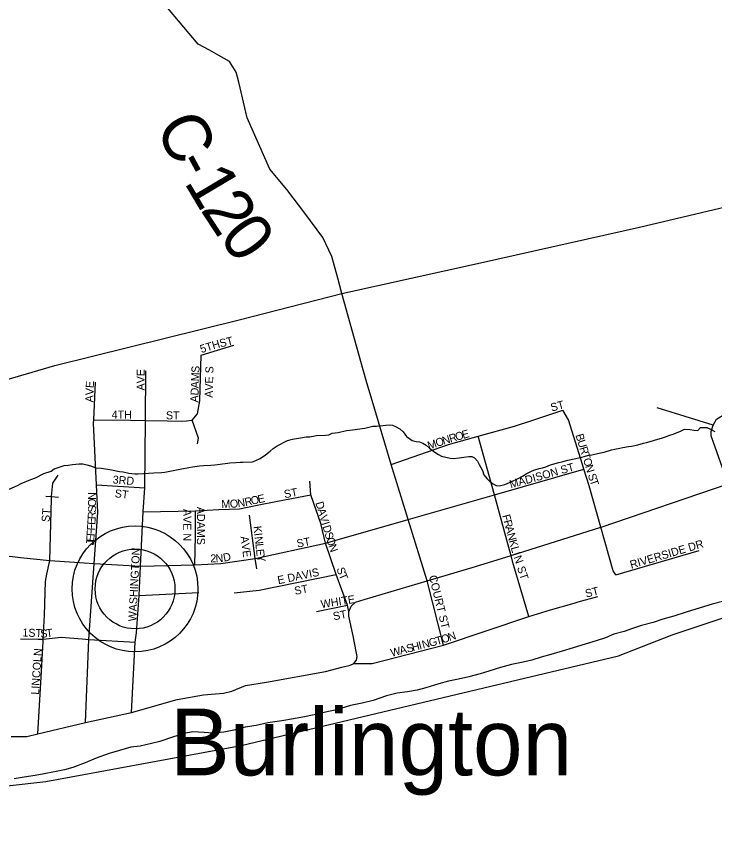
# Model space of a CAD drawing. Extents: x 0 to 34, y 0 to 22.
# Drawn here: x 6.591 to 7.417, y 14.808 to 15.766 of the extents above; entities that cross this region are included whole.
import ezdxf

# ---------------------------------------------------------------- set-up
doc = ezdxf.new("R2010")
doc.units = 0
for name, color, linetype in [('GM_X_County', 7, 'Continuous'), ('GM_X_County_Road', 7, 'Continuous'), ('GM_X_County_Road_Text', 7, 'Continuous'), ('GM_X_Major_River', 7, 'Continuous'), ('GM_X_Minor_River', 7, 'Continuous'), ('GM_X_Township', 7, 'Continuous'), ('GM_X_Township_ROW', 7, 'Continuous'), ('GM_X_Township_Subdivision', 7, 'Continuous'), ('GM_X_Township_Subdivision_Text', 7, 'Continuous'), ('GM_X_Unincorporated', 7, 'Continuous'), ('GM_X_Unincorporated_Location', 7, 'Continuous'), ('GM_X_Unincorporated_Text', 7, 'Continuous'), ('GM_X_US_Route', 7, 'Continuous')]:
    doc.layers.add(name, color=color, linetype=linetype)

msp = doc.modelspace()

# ---------------------------------------------------------------- linework, layer by layer
at = {"layer": 'GM_X_County'}
msp.add_lwpolyline([(5.81192, 14.81413), (6.12839, 14.80806), (6.29418, 14.8107), (6.34339, 14.82245), (6.49177, 14.84672), (6.62577, 14.8615), (6.85666, 14.90434), (7.30292, 15.01013), (7.36651, 15.03516), (7.82526, 15.188), (8.21322, 15.33138), (8.33283, 15.3731), (8.56485, 15.46794), (8.67596, 15.52844), (8.71954, 15.55584), (8.73927, 15.56156), (8.7787, 15.57074), (8.80562, 15.58596), (8.8602, 15.61489), (8.89736, 15.6271), (8.90844, 15.63)], dxfattribs=at)
at = {"layer": 'GM_X_County_Road'}
for points in [[(6.97083, 15.45674), (6.96374, 15.4824), (6.95339, 15.50483), (6.93213, 15.53357), (6.91086, 15.56173), (6.89067, 15.58562), (6.86378, 15.64638), (6.85395, 15.68852), (6.85092, 15.7003), (6.84296, 15.71283), (6.83047, 15.72005), (6.8191, 15.72613), (6.80585, 15.73336), (6.74869, 15.80174), (6.73004, 15.82879), (6.72032, 15.83957), (6.70903, 15.85296), (6.70404, 15.8632), (6.69721, 15.8837), (6.69035, 15.92085), (6.67921, 15.95173), (6.67768, 15.9594)], [(7.43274, 15.21354), (7.41236, 15.27022), (7.41271, 15.2754), (7.41478, 15.283), (7.41892, 15.28991), (7.42583, 15.29441), (7.43344, 15.29718), (7.46008, 15.30495), (7.46522, 15.30754), (7.46928, 15.31127), (7.47215, 15.32564), (7.4756, 15.4004), (7.47906, 15.44986), (7.48047, 15.48073), (7.48111, 15.55316)], [(7.00092, 15.34833), (6.9758, 15.43872), (6.97083, 15.45674)], [(7.07651, 15.09894), (7.05417, 15.17138), (7.0341, 15.23643), (7.01146, 15.31226), (7.00514, 15.33313), (7.00092, 15.34833)], [(6.99266, 15.00455), (6.9932, 15.00522), (6.99394, 15.00942), (6.9927, 15.01536), (6.98924, 15.0339), (6.98405, 15.05715), (6.98405, 15.0621), (6.98677, 15.06902), (6.99171, 15.07347), (7.00209, 15.07693), (7.07651, 15.09894), (7.13369, 15.11586), (7.17588, 15.12878), (7.28203, 15.16234), (7.28244, 15.16247), (7.43274, 15.21354)], [(6.58485, 14.91492), (6.60306, 14.91492), (6.61621, 14.91796), (6.67252, 14.93145), (6.72714, 14.94325), (6.78109, 14.95843), (6.81211, 14.96416), (6.83572, 14.96619), (6.84583, 14.96821), (6.86201, 14.97495), (6.88669, 14.97903), (6.9564, 14.99171), (6.97587, 14.9967), (6.98554, 14.99928), (6.98998, 15.00126), (6.99266, 15.00455)]]:
    msp.add_lwpolyline(points, dxfattribs=at)
at = {"layer": 'GM_X_Major_River'}
for points in [[(7.42732, 15.07476), (7.4137, 15.07135), (7.39933, 15.0668), (7.38307, 15.06187), (7.36832, 15.05695), (7.35546, 15.05354), (7.34374, 15.04975), (7.33012, 15.04596), (7.31953, 15.04255), (7.3097, 15.03914), (7.29722, 15.03574), (7.28739, 15.03157), (7.27642, 15.02778), (7.26356, 15.02399), (7.24919, 15.01982), (7.23633, 15.01566), (7.2231, 15.01187), (7.21137, 15.00846), (7.20041, 15.00505), (7.19019, 15.00278), (7.1762, 14.99975), (7.16334, 14.99634), (7.14973, 14.99217), (7.13914, 14.98876), (7.12591, 14.98535), (7.1138, 14.9827), (7.10208, 14.98005), (7.09036, 14.97702), (7.07523, 14.97248), (7.06464, 14.96945), (7.0533, 14.96755), (7.04119, 14.96604), (7.02871, 14.96301), (7.01283, 14.95733), (6.99997, 14.9543), (6.98598, 14.95127), (6.96934, 14.94634), (6.95648, 14.94369), (6.94665, 14.94104), (6.93341, 14.93839), (6.91866, 14.93574), (6.90467, 14.93347), (6.88841, 14.93082), (6.87442, 14.92779), (6.86156, 14.9259), (6.84794, 14.92249), (6.83622, 14.91984), (6.82336, 14.91871), (6.81278, 14.91947), (6.79954, 14.92023), (6.78933, 14.91834), (6.77534, 14.91417), (6.76059, 14.90887), (6.75076, 14.9066), (6.73714, 14.90357), (6.72617, 14.90205), (6.71294, 14.89827), (6.70045, 14.89486), (6.68533, 14.88917), (6.67209, 14.88349), (6.65772, 14.87819)], [(6.65772, 14.87819), (6.64789, 14.87553), (6.63578, 14.87288), (6.62368, 14.87061), (6.61309, 14.86872), (6.60024, 14.86683), (6.58813, 14.86494)]]:
    msp.add_lwpolyline(points, dxfattribs=at)
at = {"layer": 'GM_X_Minor_River'}
for points in [[(6.58251, 15.20737), (6.59205, 15.21176), (6.59664, 15.21396), (6.60809, 15.2187), (6.61342, 15.22051), (6.62336, 15.22565), (6.63212, 15.22854), (6.63558, 15.23114), (6.64739, 15.23512), (6.65195, 15.2358), (6.65726, 15.23647), (6.66106, 15.23678), (6.66523, 15.23709), (6.66939, 15.23702), (6.6743, 15.23617), (6.67845, 15.23496), (6.68484, 15.23258), (6.69127, 15.23209), (6.69883, 15.23082), (6.70336, 15.22998), (6.7128, 15.2283), (6.71734, 15.22784), (6.72375, 15.22622), (6.73093, 15.22533), (6.73472, 15.22527), (6.74761, 15.22619), (6.7533, 15.22647), (6.7624, 15.22707), (6.76657, 15.22738), (6.77417, 15.22877), (6.78216, 15.23053), (6.78671, 15.23121), (6.7947, 15.23298), (6.79926, 15.23366), (6.80723, 15.23466), (6.81216, 15.23534), (6.82088, 15.23556), (6.82543, 15.23587), (6.82885, 15.23657), (6.83796, 15.23755), (6.84327, 15.23822), (6.85048, 15.23886), (6.85541, 15.23915), (6.85882, 15.23909), (6.87019, 15.23966), (6.87401, 15.24111), (6.87898, 15.24368), (6.88549, 15.24775), (6.89087, 15.25221), (6.89471, 15.25519), (6.89931, 15.25852), (6.91154, 15.26477), (6.91725, 15.26619), (6.92675, 15.26793), (6.93359, 15.26895), (6.93776, 15.26926), (6.94573, 15.27064), (6.95635, 15.27122), (6.96052, 15.27153), (6.96434, 15.27336), (6.97156, 15.27438), (6.98144, 15.27648), (6.98524, 15.27718), (6.99169, 15.27783), (6.99967, 15.27883), (7.00309, 15.27953), (7.01222, 15.28165), (7.01676, 15.28158), (7.02094, 15.28226), (7.02435, 15.28259), (7.02777, 15.28291), (7.03232, 15.28321), (7.03572, 15.28277), (7.0391, 15.28119), (7.04435, 15.27845), (7.04808, 15.27496), (7.05215, 15.26958), (7.05889, 15.26491), (7.06379, 15.26368), (7.06757, 15.26324), (7.07171, 15.26165), (7.07545, 15.25931), (7.07956, 15.25582), (7.08592, 15.25116), (7.09003, 15.24805), (7.09378, 15.24608), (7.09869, 15.24524), (7.10397, 15.24401), (7.10775, 15.24357), (7.11458, 15.24421), (7.1199, 15.24526), (7.12597, 15.24591), (7.12938, 15.24585), (7.13276, 15.24428), (7.1361, 15.24042)], [(7.1361, 15.24042), (7.1383, 15.23621), (7.14197, 15.22931), (7.14378, 15.22434), (7.1471, 15.21973), (7.1512, 15.21586), (7.15457, 15.21353), (7.15832, 15.21157), (7.16172, 15.21113), (7.16857, 15.21291), (7.17659, 15.21619), (7.18346, 15.21949), (7.18958, 15.2228), (7.19379, 15.22539), (7.20067, 15.22907), (7.2041, 15.23015), (7.20905, 15.23158), (7.21324, 15.23265), (7.21704, 15.23372), (7.22238, 15.23591), (7.23228, 15.23878), (7.23608, 15.23947), (7.24294, 15.24163), (7.25244, 15.24337), (7.25967, 15.24515), (7.26804, 15.24728), (7.27146, 15.24798), (7.27792, 15.24939), (7.28591, 15.25115), (7.29466, 15.25366), (7.29809, 15.25436), (7.30455, 15.25577), (7.30797, 15.25647), (7.31481, 15.25787), (7.31823, 15.25819), (7.32583, 15.25958), (7.33268, 15.26174), (7.3361, 15.26244), (7.34333, 15.26422), (7.34677, 15.26568), (7.35361, 15.26746), (7.35743, 15.26891), (7.36353, 15.27109), (7.36771, 15.27216), (7.37611, 15.27581), (7.38107, 15.278), (7.38751, 15.27789), (7.39204, 15.27706), (7.39658, 15.2766), (7.40004, 15.27996), (7.40725, 15.28021), (7.41176, 15.27824), (7.41701, 15.27549)]]:
    msp.add_lwpolyline(points, dxfattribs=at)
at = {"layer": 'GM_X_Township'}
msp.add_lwpolyline([(5.81192, 14.81413), (6.12839, 14.80806), (6.29418, 14.8107), (6.34339, 14.82245), (6.49177, 14.84672), (6.62577, 14.8615), (6.85666, 14.90434), (7.30292, 15.01013), (7.36651, 15.03516), (7.82526, 15.188), (8.21322, 15.33138), (8.33283, 15.3731), (8.56485, 15.46794), (8.67596, 15.52844), (8.71954, 15.55584), (8.73927, 15.56156), (8.7787, 15.57074), (8.80562, 15.58596), (8.8602, 15.61489), (8.89736, 15.6271), (8.90844, 15.63)], dxfattribs=at)
at = {"layer": 'GM_X_Township_ROW'}
msp.add_lwpolyline([(7.41478, 15.283), (7.34853, 15.30357)], dxfattribs=at)
at = {"layer": 'GM_X_Township_Subdivision'}
for points in [[(6.80958, 15.36552), (6.84821, 15.37763)], [(6.80501, 15.26077), (6.80615, 15.2676), (6.79858, 15.28885), (6.80501, 15.29644), (6.80767, 15.31162), (6.80958, 15.36552)], [(6.72714, 14.94325), (6.73119, 15.02622), (6.73287, 15.03735), (6.73625, 15.08154), (6.73778, 15.1162), (6.74064, 15.18055), (6.74291, 15.20866), (6.74356, 15.28837), (6.74404, 15.34696)], [(6.68225, 15.2858), (6.68242, 15.28929), (6.68456, 15.33371)], [(7.20034, 15.28849), (7.23713, 15.30057)], [(7.26018, 15.23651), (7.24396, 15.28903), (7.23713, 15.30057)], [(6.68242, 15.28929), (6.726, 15.28864)], [(6.726, 15.28864), (6.72607, 15.28863), (6.74356, 15.28837), (6.76958, 15.28798)], [(6.76958, 15.28798), (6.76972, 15.28798), (6.78645, 15.28772), (6.79214, 15.28809), (6.79858, 15.28885)], [(7.0341, 15.23643), (7.10206, 15.25995), (7.13711, 15.26979), (7.17985, 15.28176), (7.20034, 15.28849)], [(6.67252, 14.93145), (6.67657, 15.0296), (6.68293, 15.11931), (6.6872, 15.17964), (6.68565, 15.21245), (6.68222, 15.28518), (6.68225, 15.2858)], [(7.17444, 15.13407), (7.15631, 15.20063), (7.13711, 15.26979)], [(6.95662, 15.14343), (7.05417, 15.17138), (7.15631, 15.20063), (7.26192, 15.23088)], [(7.29964, 15.10583), (7.29652, 15.11068), (7.28203, 15.16234), (7.26833, 15.21121), (7.26192, 15.23088), (7.26018, 15.23651)], [(6.63249, 15.19572), (6.63257, 15.1985), (6.63412, 15.21417), (6.64031, 15.22365)], [(6.68565, 15.21245), (6.74291, 15.20866)], [(6.95133, 15.1649), (6.9512, 15.16542), (6.93912, 15.2005), (6.93776, 15.21682)], [(6.89982, 15.19292), (6.93912, 15.2005)], [(6.62558, 15.199), (6.63257, 15.1985), (6.64069, 15.19792)], [(6.62707, 15.10655), (6.63045, 15.12287), (6.63249, 15.19572)], [(6.74064, 15.18055), (6.80272, 15.18145), (6.83037, 15.18327), (6.85484, 15.18418), (6.87568, 15.18826), (6.89982, 15.19292)], [(6.80185, 15.11781), (6.80272, 15.15154), (6.80272, 15.18145)], [(6.8751, 15.11303), (6.87345, 15.12539), (6.86662, 15.17665)], [(6.98405, 15.0621), (6.9823, 15.07008), (6.96899, 15.10654), (6.95662, 15.14343), (6.95133, 15.1649)], [(6.63045, 15.12287), (6.68293, 15.11931), (6.68333, 15.11929), (6.73778, 15.1162), (6.80185, 15.11781), (6.83263, 15.11929), (6.87345, 15.12539), (6.95662, 15.14343)], [(6.34065, 15.14003), (6.44593, 15.13373), (6.46713, 15.13233), (6.49, 15.12937), (6.50238, 15.12676), (6.52289, 15.12513), (6.55188, 15.12546), (6.5685, 15.12638), (6.58315, 15.12807), (6.59556, 15.12663), (6.63045, 15.12287)], [(7.19695, 15.05686), (7.17812, 15.12055), (7.17588, 15.12878), (7.17444, 15.13407)], [(7.29964, 15.10583), (7.39843, 15.13467)], [(6.62247, 15.02721), (6.62262, 15.02993), (6.6243, 15.05827), (6.62531, 15.09807), (6.62707, 15.10655)], [(6.84854, 15.08482), (6.87809, 15.08784), (6.96899, 15.10654)], [(7.09611, 15.02296), (7.07651, 15.09894)], [(6.73625, 15.08154), (6.80671, 15.08524)], [(7.25058, 15.07263), (7.25508, 15.07396), (7.27859, 15.08038)], [(6.94597, 15.06242), (6.9823, 15.07008)], [(7.2227, 15.06443), (7.25058, 15.07263)], [(6.98998, 15.00126), (7.01171, 15.00097), (7.09611, 15.02296), (7.19695, 15.05686), (7.2227, 15.06443)], [(6.59564, 15.03027), (6.61655, 15.02996)], [(6.61655, 15.02996), (6.61823, 15.02993), (6.62262, 15.02993), (6.64386, 15.03229), (6.6686, 15.03025)], [(6.6686, 15.03025), (6.67657, 15.0296), (6.73119, 15.02622)], [(6.61621, 14.91796), (6.62059, 14.99182), (6.62247, 15.02721)]]:
    msp.add_lwpolyline(points, dxfattribs=at)
at = {"layer": 'GM_X_Unincorporated'}
for radius in [0.0744, 0.04716]:
    msp.add_circle((6.73121, 15.08929), radius, dxfattribs=at)
at = {"layer": 'GM_X_Unincorporated_Location'}
msp.add_line((6.73121, 15.08929), (6.73121, 15.08929), dxfattribs=at)
at = {"layer": 'GM_X_US_Route'}
msp.add_lwpolyline([(6.06926, 15.17982), (6.17161, 15.21295), (6.48951, 15.31069), (6.63625, 15.35347), (6.85428, 15.40737), (6.9758, 15.43872), (7.13959, 15.47493), (7.32779, 15.51719), (7.48111, 15.55316), (7.56574, 15.57231), (7.56968, 15.57321), (7.66601, 15.59649), (7.73616, 15.61621), (7.92957, 15.69717), (8.00724, 15.73447)], dxfattribs=at)

# ---------------------------------------------------------------- texts
at = {"layer": 'GM_X_County_Road_Text'}
for s, rotation, p in [('C', 297.47182, (6.75421, 15.63516)), ('-', 298.40847, (6.77622, 15.59286)), ('1', 300.6802, (6.78853, 15.57019)), ('2', 303.25591, (6.80786, 15.53772)), ('0', 306.86233, (6.8293, 15.50526))]:
    msp.add_text(s, height=0.05682, rotation=rotation, dxfattribs=at).set_placement(p)
at = {"layer": 'GM_X_Township_Subdivision_Text'}
for s, height, rotation, p in [('5TH', 0.00947, 16.92589, (6.80969, 15.36809)), ('ST', 0.00947, 14.03423, (6.83227, 15.37478)), ('AVE', 0.00947, 90, (6.74259, 15.32389)), ('M', 0.00947, 87.70445, (6.80685, 15.3346)), ('S', 0.00947, 87.70789, (6.80725, 15.3446)), ('AVE S', 0.00947, 88.56869, (6.82304, 15.31519)), ('AVE', 0.00947, 88.02615, (6.68176, 15.30978)), ('A', 0.00947, 87.72057, (6.80652, 15.32628)), ('D', 0.00947, 87.72633, (6.80619, 15.31795)), ('A', 0.00947, 88.16372, (6.80592, 15.30964)), ('ST', 0.00947, 14.93181, (7.22391, 15.29894)), ('4TH', 0.00947, 0.00001, (6.70354, 15.29067)), ('ST', 0.00947, 0.00001, (6.76771, 15.28984)), ('E', 0.00947, 16.19886, (7.11926, 15.26662)), ('O', 0.00947, 18.40845, (7.0883, 15.25707)), ('N', 0.00947, 17.62071, (7.09617, 15.25969)), ('R', 0.00947, 16.30708, (7.10406, 15.2622)), ('O', 0.00947, 16.18459, (7.11125, 15.2643)), ('B', 0.00947, 287.30984, (7.25191, 15.27108)), ('M', 0.00947, 18.40741, (7.07881, 15.25391)), ('U', 0.00947, 287.31092, (7.25414, 15.26392)), ('R', 0.00947, 287.28576, (7.25662, 15.25596)), ('T', 0.00947, 287.33189, (7.25885, 15.2488)), ('MADISON ST', 0.00947, 15.66872, (7.17556, 15.2081)), ('O', 0.00947, 287.30942, (7.26084, 15.24243)), ('N', 0.00947, 287.28815, (7.26332, 15.23448)), ('3RD', 0.00947, 355.60152, (6.70451, 15.214)), ('S', 0.00947, 287.31039, (7.26654, 15.22413)), ('T', 0.00947, 289.13917, (7.26863, 15.21745)), ('N', 0.00947, 89.99557, (6.68509, 15.19459)), ('ST', 0.00947, 352.87456, (6.70674, 15.19783)), ('E', 0.00947, 12.19564, (6.87727, 15.19048)), ('ST', 0.00947, 10.618, (6.90821, 15.19647)), ('O', 0.00947, 89.95193, (6.68508, 15.18624)), ('M', 0.00947, 2.33438, (6.83347, 15.18484)), ('O', 0.00947, 2.49153, (6.8435, 15.18524)), ('N', 0.00947, 9.03961, (6.853, 15.18573)), ('R', 0.00947, 12.15796, (6.86178, 15.18714)), ('O', 0.00947, 12.19877, (6.86912, 15.18872)), ('D', 0.00947, 286.62467, (6.94441, 15.19106)), ('ST', 0.00947, 86.4256, (6.6301, 15.16817)), ('S', 0.00947, 89.11504, (6.68498, 15.17943)), ('AVE N', 0.00947, 270, (6.7882, 15.18389)), ('ADAMS', 0.00947, 270, (6.80449, 15.18639)), ('A', 0.00947, 286.62447, (6.9468, 15.18308)), ('E', 0.00947, 86.3614, (6.68413, 15.16479)), ('R', 0.00947, 86.8391, (6.68455, 15.17153)), ('V', 0.00947, 286.62447, (6.94918, 15.17509)), ('F', 0.00947, 285.03394, (7.16526, 15.17601)), ('F', 0.00947, 86.36385, (6.6837, 15.15814)), ('K', 0.00947, 276.37339, (6.87114, 15.16325)), ('I', 0.00947, 286.62428, (6.95157, 15.16711)), ('D', 0.00947, 286.62447, (6.95276, 15.16312)), ('R', 0.00947, 285.00984, (7.16699, 15.16958)), ('A', 0.00947, 285.02412, (7.16893, 15.16233)), ('E', 0.00947, 86.3639, (6.68286, 15.14483)), ('F', 0.00947, 86.38042, (6.68328, 15.15148)), ('I', 0.00947, 276.35167, (6.87207, 15.15497)), ('S', 0.00947, 286.62418, (6.95514, 15.15513)), ('N', 0.00947, 285.0342, (7.1711, 15.15428)), ('J', 0.00947, 86.36938, (6.6826, 15.14067)), ('AVE', 0.00947, 277.84905, (6.85583, 15.15107)), ('N', 0.00947, 276.38631, (6.87253, 15.15082)), ('L', 0.00947, 276.35152, (6.87346, 15.14254)), ('ST', 0.00947, 10.62007, (6.92321, 15.13814)), ('O', 0.00947, 287.78845, (6.95711, 15.14854)), ('N', 0.00947, 289.55849, (6.95976, 15.1403)), ('K', 0.00947, 285.01238, (7.17326, 15.14623)), ('RIVERSIDE DR', 0.0094697, 16.5259, (7.31803, 15.1131)), ('WASHINGTON', 0.00947, 86.98617, (6.73259, 15.05066)), ('E', 0.00947, 276.39538, (6.87419, 15.13591)), ('L', 0.00947, 285.38393, (7.17544, 15.13812)), ('I', 0.00947, 288.14651, (7.17735, 15.13122)), ('2', 0.00947, 0.30638, (6.82022, 15.12067)), ('N', 0.00947, 3.85837, (6.82669, 15.12072)), ('D', 0.00947, 11.09542, (6.8363, 15.12146)), ('Y', 0.00947, 280.43619, (6.87504, 15.12858)), ('N', 0.00947, 290.68365, (7.17879, 15.12682)), ('E DAVIS', 0.00947, 11.72485, (6.90068, 15.0948)), ('S', 0.00947, 285.96933, (6.96946, 15.11341)), ('ST', 0.00947, 288.42553, (7.18273, 15.11445)), ('T', 0.00947, 292.94704, (6.97171, 15.10581)), ('COURT ST', 0.00947, 283.82768, (7.07861, 15.10432)), ('ST', 0.00947, 11.31046, (6.92055, 15.08216)), ('ST', 0.00947, 14.03745, (7.26477, 15.07895)), ('WHITE', 0.00947, 8.84228, (6.9516, 15.06648)), ('ST', 0.00947, 10.62048, (6.96621, 15.05213)), ('1ST', 0.00947, 357.5102, (6.59779, 15.03317)), ('S', 0.00947, 4.20591, (6.61956, 15.03151)), ('T', 0.00947, 6.86401, (6.62668, 15.03205)), ('N', 0.00947, 19.28415, (7.10313, 15.02742)), ('I', 0.00947, 14.60471, (7.06782, 15.01756)), ('N', 0.00947, 14.60108, (7.07185, 15.01861)), ('G', 0.00947, 14.59933, (7.07991, 15.02072)), ('T', 0.00947, 15.18928, (7.08807, 15.02284)), ('O', 0.00947, 18.28862, (7.09505, 15.02475)), ('LINCOLN', 0.00947, 86.24675, (6.61759, 14.96401)), ('W', 0.00947, 14.60606, (7.03476, 15.00895)), ('A', 0.00947, 14.61177, (7.04524, 15.01168)), ('S', 0.00947, 14.612, (7.0533, 15.01378)), ('H', 0.00947, 14.60406, (7.05975, 15.01546))]:
    msp.add_text(s, height=height, rotation=rotation, dxfattribs=at).set_placement(p)
at = {"layer": 'GM_X_Unincorporated_Text'}
msp.add_text('Burlington', height=0.078977, rotation=0.00001, dxfattribs=at).set_placement((6.77271, 14.86885))

doc.saveas('drawing.dxf')
